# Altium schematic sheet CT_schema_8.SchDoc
size 274 x 160 mm
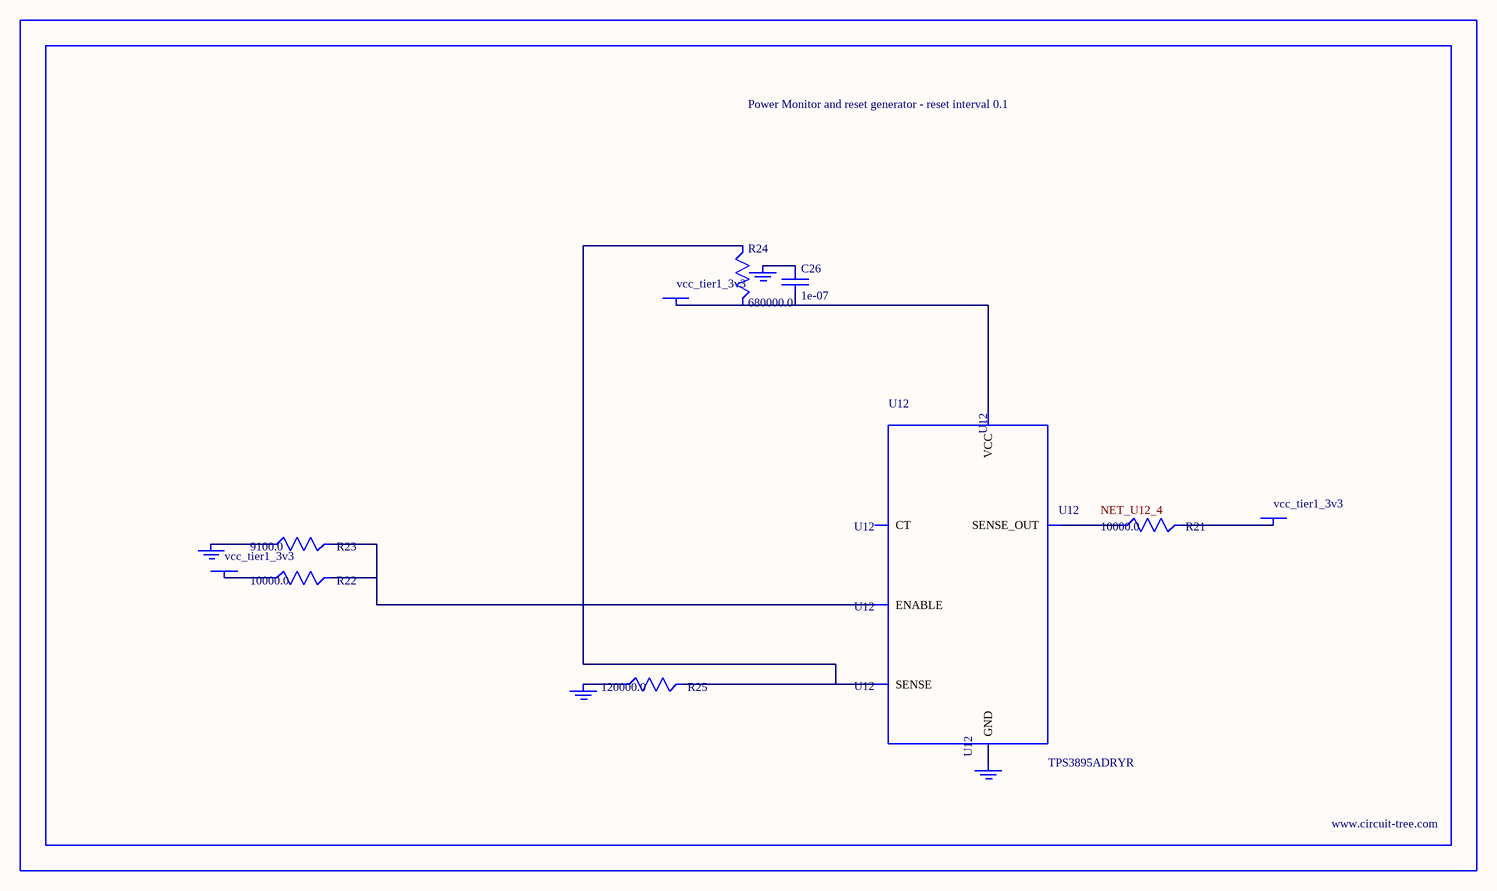
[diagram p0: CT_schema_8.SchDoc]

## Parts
BORDER7  (no value)
C26  1e-07  [C0402]
GND_INSTANCE_7_0  (no value)
GND_INSTANCE_7_1  (no value)
GND_INSTANCE_7_2  (no value)
GND_INSTANCE_7_3  (no value)
POWER_INSTANCE_7_0  vcc_tier1_3v3
POWER_INSTANCE_7_1  vcc_tier1_3v3
POWER_INSTANCE_7_2  vcc_tier1_3v3
R21  10000.0  [R0603]
R22  10000.0  [R0603]
R23  9100.0  [R0603]
R24  680000.0  [R0603]
R25  120000.0  [R0603]
U12  TPS3895ADRYR  [SON-6]

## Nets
NetC26_1: C26.1 GND_INSTANCE_7_2.0(GND)
NetC26_2: C26.2 POWER_INSTANCE_7_2.0(PWR) R24.2 U12.6(VCC)
NetGND_INSTANCE_7_0_0: GND_INSTANCE_7_0.0(GND) R23.1
NetGND_INSTANCE_7_1_0: GND_INSTANCE_7_1.0(GND) R25.1
NetGND_INSTANCE_7_3_0: GND_INSTANCE_7_3.0(GND) U12.2(GND)
NetPOWER_INSTANCE_7_0_0: POWER_INSTANCE_7_0.0(PWR) R22.1
NetPOWER_INSTANCE_7_1_0: POWER_INSTANCE_7_1.0(PWR) R21.2
NetR21_1: R21.1 U12.4(SENSE_OUT)
NetR22_2: R22.2 R23.2 U12.1(ENABLE)
NetR24_1: R24.1 R25.2 U12.3(SENSE)

Not connected (* = marked no-connect by the designer): U12 5(CT)

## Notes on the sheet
- Labels drawn without touching a wire or pin: NET_U12_4

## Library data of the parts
BORDER7 = BORDER_PAGE7
C26 = C0402C104K3RACTU
GND_INSTANCE_7_0-GND_INSTANCE_7_3 = GND
POWER_INSTANCE_7_0-POWER_INSTANCE_7_2 = PWR
R21 R22 = RC0603JR-0710KL
R23 = RC0603JR-079K1L
R24 = RC0603JR-07680KL
R25 = RC0603JR-07120KL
